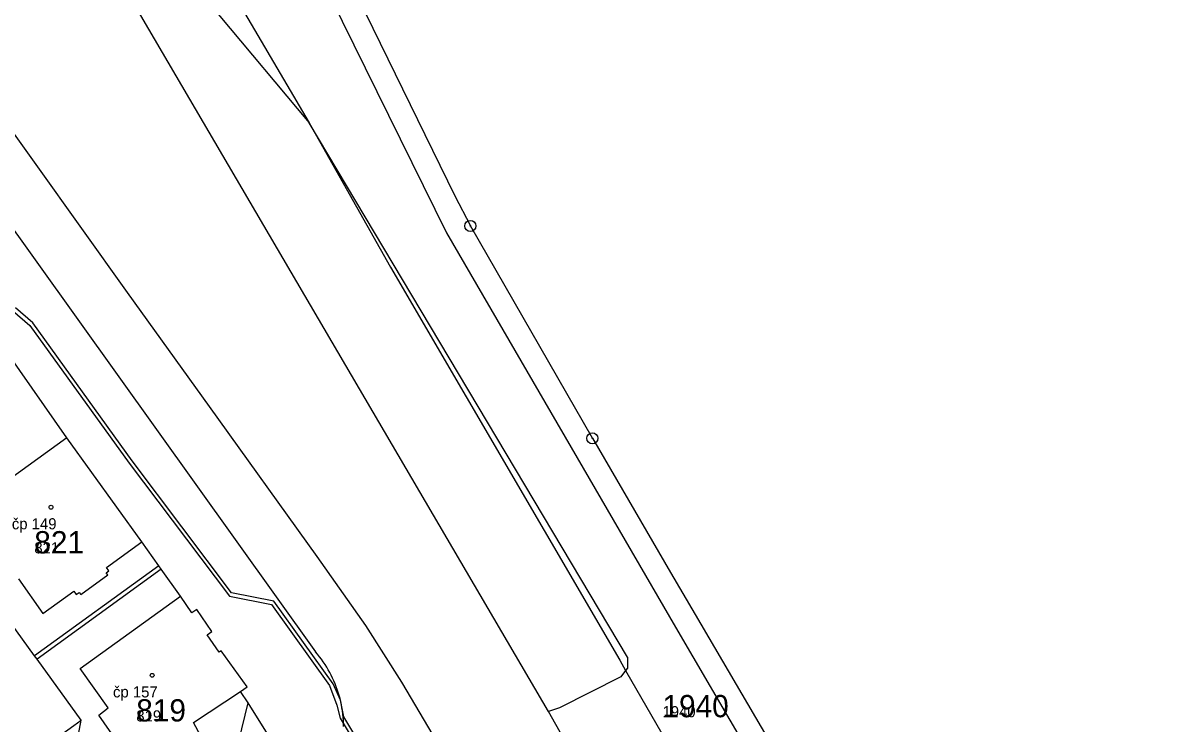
# Model space of a CAD drawing. Extents: x -763628 to -761565, y -976033 to -973833.
# Drawn here: x -761992.5 to -761889.1, y -974657.9 to -974594.9 of the extents above; entities that cross this region are included whole.
import ezdxf

# ---------------------------------------------------------------- set-up
doc = ezdxf.new("R2010")
doc.units = 0
for name, color, linetype in [('KN_cisla parcel 1000', 7, 'Continuous'), ('KN_cisla parcel 500', 7, 'Continuous'), ('KN_cisla popisna 500', 7, 'Continuous'), ('KN_hranice parcel', 7, 'Continuous'), ('KN_hranice uzemi', 7, 'Continuous'), ('KN_vecna bremena', 7, 'Continuous'), ('KN_vnitrni kresba parcel', 7, 'Continuous'), ('KN_znacky bodu BP', 7, 'Continuous'), ('KN_znacky budov', 7, 'Continuous')]:
    doc.layers.add(name, color=color, linetype=linetype)

msp = doc.modelspace()

# ---------------------------------------------------------------- linework, layer by layer
at = {"layer": 'KN_hranice parcel'}
for p, q in [((-761988.51, -974632.17), (-761995.71, -974621.9)), ((-761980.03, -974643.96), (-761991.19, -974652.06)), ((-761987.24, -974657.54), (-761991.19, -974652.06))]:
    msp.add_line(p, q, dxfattribs=at)
for points in [[(-761810.08, -974915.63), (-761823.04, -974895.41), (-761834.04, -974877.31), (-761858.31, -974831.88), (-761872.33, -974801.33), (-761885.74, -974772.85), (-761886.88, -974770.42), (-761917.51, -974705.34), (-761920.67, -974699.09), (-761941.43, -974663.54), (-761945.24, -974656.74), (-761990.97, -974578.65), (-761992.27, -974576.42), (-761994.77, -974571.81), (-761997.35, -974565.98), (-761999.32, -974560.94)], [(-761987.47, -974568.32), (-761982.71, -974576.56), (-761978.88, -974583.19), (-761966.76, -974603.87), (-761959.45, -974616.82), (-761938.85, -974652.15), (-761938.32, -974653.07), (-761934.62, -974659.51), (-761914.18, -974695.15), (-761910.87, -974701.59), (-761879.94, -974767.27), (-761878.77, -974769.75), (-761865.49, -974797.95), (-761861.06, -974806.66), (-761850.83, -974828.32), (-761826.84, -974873.29), (-761815.87, -974891.33), (-761810.46, -974899.49), (-761803.28, -974910.43)], [(-761988.51, -974632.17), (-761997.78, -974638.84), (-761999.28, -974639.91), (-762002.68, -974642.4)], [(-761980.03, -974643.96), (-761980.25, -974643.66), (-761981.79, -974641.51), (-761988.51, -974632.17)], [(-761972.22, -974655.96), (-761972.93, -974654.96), (-761972.31, -974654.55), (-761974.66, -974651.3), (-761974.83, -974651.41), (-761975.9, -974649.87), (-761975.48, -974649.58), (-761976.85, -974647.58), (-761977.28, -974647.88), (-761978.32, -974646.39), (-761980.03, -974643.96)], [(-761991.19, -974652.06), (-761991.41, -974651.76), (-761994.12, -974648.01), (-761999.94, -974646.87), (-762001.47, -974646.59), (-762004.15, -974646.1)], [(-761979.69, -974669.73), (-761979.91, -974669.31), (-761981.69, -974666.66), (-761980.99, -974666.29), (-761977.97, -974664.66), (-761977.88, -974664.84), (-761974.34, -974662.95), (-761974.69, -974662.3), (-761973.64, -974661.76), (-761972.22, -974655.96)], [(-761969.04, -974661.12), (-761969.3, -974660.69), (-761972.22, -974655.96)], [(-761998.26, -974665.47), (-761996.84, -974664.44), (-761987.89, -974658.01), (-761987.24, -974657.54)], [(-761981.3, -974670.56), (-761987.91, -974661.23), (-761987.24, -974657.54)]]:
    msp.add_lwpolyline(points, dxfattribs=at)
at = {"layer": 'KN_hranice uzemi'}
for p, q in [((-761963.91, -974589.47), (-761953.66, -974610.44)), ((-761953.66, -974610.44), (-761952.27, -974613.13)), ((-761941.31, -974632.21), (-761952.27, -974613.13))]:
    msp.add_line(p, q, dxfattribs=at)
for points in [[(-761941.31, -974632.21), (-761934.28, -974644.27), (-761932.08, -974648.04)], [(-761932.08, -974648.04), (-761923.68, -974662.34), (-761922.32, -974664.67)]]:
    msp.add_lwpolyline(points, dxfattribs=at)
at = {"layer": 'KN_vecna bremena'}
for points in [[(-761993.39, -974620.72), (-761991.83, -974622.08), (-761982.93, -974634.44), (-761973.92, -974646.4), (-761970.13, -974647.15), (-761964.92, -974654.43), (-761964.25, -974656.19), (-761963.97, -974657.36), (-761954.08, -974673.83), (-761952.72, -974674.55), (-761951.61, -974676.29), (-761949.41, -974679.84), (-761946.42, -974684.86), (-761946.33, -974685.75)], [(-761953.84, -974673.57), (-761963.65, -974657.22), (-761963.94, -974655.74), (-761964.6, -974654.27), (-761969.93, -974646.83), (-761973.72, -974646.08), (-761982.65, -974634.24), (-761991.57, -974621.84), (-761993.13, -974620.48)]]:
    msp.add_lwpolyline(points, dxfattribs=at)
at = {"layer": 'KN_vnitrni kresba parcel'}
for p, q in [((-761979.04, -974563.76), (-761954.41, -974613.75)), ((-761974.93, -974594.1), (-761966.76, -974603.87)), ((-761999.86, -974595.7), (-761991.3, -974607.61)), ((-762003.75, -974598.88), (-761966.17, -974651.4)), ((-761938.16, -974651.87), (-761966.76, -974603.87)), ((-761991.3, -974607.61), (-761983.09, -974619.1)), ((-761954.41, -974613.75), (-761933.84, -974649.19)), ((-761983.09, -974619.1), (-761975.74, -974629.34)), ((-761975.74, -974629.34), (-761966.07, -974642.84)), ((-761984.96, -974643.81), (-761981.79, -974641.51)), ((-761980.25, -974643.66), (-761991.41, -974651.76)), ((-761966.07, -974642.84), (-761961.69, -974649.02)), ((-761987.27, -974646.23), (-761984.84, -974644.48)), ((-761984.98, -974644.29), (-761984.74, -974644.11)), ((-761984.84, -974644.48), (-761984.98, -974644.29)), ((-761984.74, -974644.11), (-761984.96, -974643.81)), ((-761992.87, -974644.82), (-761990.69, -974647.95)), ((-761990.69, -974647.95), (-761987.89, -974645.93)), ((-761987.89, -974645.93), (-761987.67, -974646.24)), ((-761987.67, -974646.24), (-761987.41, -974646.05)), ((-761987.41, -974646.05), (-761987.27, -974646.23)), ((-761987.31, -974652.88), (-761978.32, -974646.39)), ((-761961.69, -974649.02), (-761958.45, -974654.13)), ((-761933.84, -974649.19), (-761907.12, -974694.89)), ((-761938.16, -974651.87), (-761938.16, -974652.87)), ((-761984.8, -974656.41), (-761987.31, -974652.88)), ((-761938.16, -974652.87), (-761938.32, -974653.07)), ((-761938.76, -974653.64), (-761944.25, -974656.42)), ((-761938.32, -974653.07), (-761938.76, -974653.64)), ((-761977.13, -974657.74), (-761972.93, -974654.96)), ((-761958.45, -974654.13), (-761944.08, -974678.46)), ((-761985.64, -974657.07), (-761984.8, -974656.41)), ((-761984, -974659.45), (-761985.64, -974657.07)), ((-761944.25, -974656.42), (-761945.24, -974656.74)), ((-761974.69, -974662.3), (-761977.13, -974657.74))]:
    msp.add_line(p, q, dxfattribs=at)
msp.add_lwpolyline([(-761963.66, -974658.11), (-761963.67, -974657.82), (-761963.68, -974657.54), (-761963.7, -974657.26), (-761963.72, -974656.98), (-761963.76, -974656.7), (-761963.8, -974656.43), (-761963.85, -974656.15), (-761963.91, -974655.87), (-761963.97, -974655.6), (-761964.05, -974655.33), (-761964.13, -974655.06), (-761964.22, -974654.79), (-761964.31, -974654.53), (-761964.41, -974654.26), (-761964.52, -974654.01), (-761964.64, -974653.75), (-761964.76, -974653.5), (-761964.89, -974653.25), (-761965.03, -974653), (-761965.17, -974652.76), (-761965.32, -974652.52), (-761965.48, -974652.29), (-761965.64, -974652.06), (-761965.81, -974651.84), (-761965.99, -974651.61), (-761966.17, -974651.4)], dxfattribs=at)
at = {"layer": 'KN_znacky bodu BP'}
for centre, radius in [((-761952.27, -974613.13), 0.5), ((-761952.27, -974613.13), 0.0303), ((-761941.31, -974632.21), 0.5), ((-761941.31, -974632.21), 0.0303)]:
    msp.add_circle(centre, radius, dxfattribs=at)
at = {"layer": 'KN_znacky budov'}
for centre in [(-761989.94, -974638.4), (-761980.85, -974653.5)]:
    msp.add_circle(centre, 0.175, dxfattribs=at)

# ---------------------------------------------------------------- texts
at = {"layer": 'KN_cisla parcel 1000'}
for s, p in [('821', (-761991.44, -974642.55)), ('819', (-761982.28, -974657.65)), ('1940', (-761935.01, -974657.27))]:
    msp.add_text(s, height=2, dxfattribs=at).set_placement(p)
at = {"layer": 'KN_cisla parcel 500'}
for s, p in [('821', (-761991.44, -974642.55)), ('819', (-761982.28, -974657.65)), ('1940', (-761935.01, -974657.27))]:
    msp.add_text(s, height=1, dxfattribs=at).set_placement(p)
at = {"layer": 'KN_cisla popisna 500'}
for s, p in [('čp 149', (-761993.46, -974640.39)), ('čp 157', (-761984.37, -974655.49))]:
    msp.add_text(s, height=1, dxfattribs=at).set_placement(p)

doc.saveas('drawing.dxf')
